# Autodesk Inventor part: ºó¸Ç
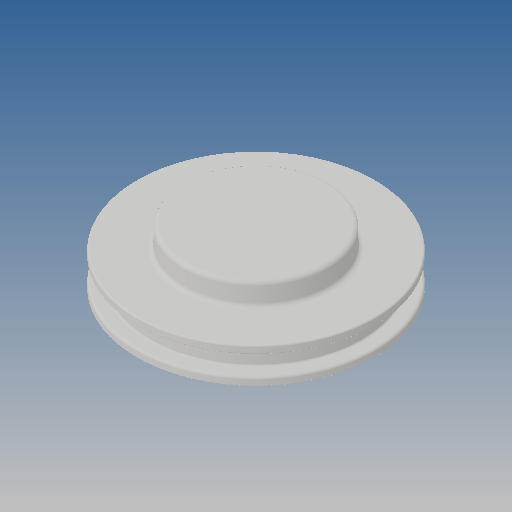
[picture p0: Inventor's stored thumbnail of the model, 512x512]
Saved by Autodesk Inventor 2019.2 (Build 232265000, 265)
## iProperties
Created: 2013-07
Part Number: ºó¸Ç
Material: Ogólny
Document SubType Name: Modeling
Designer: CADENGINEERING4
Density: 1 g/cm^3
Appearance: Domyślna
Author: CADENGINEERING4
Revision Number: ÈÎºÎ
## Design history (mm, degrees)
feature "Ðý×ª1"
node "Bryła1"
